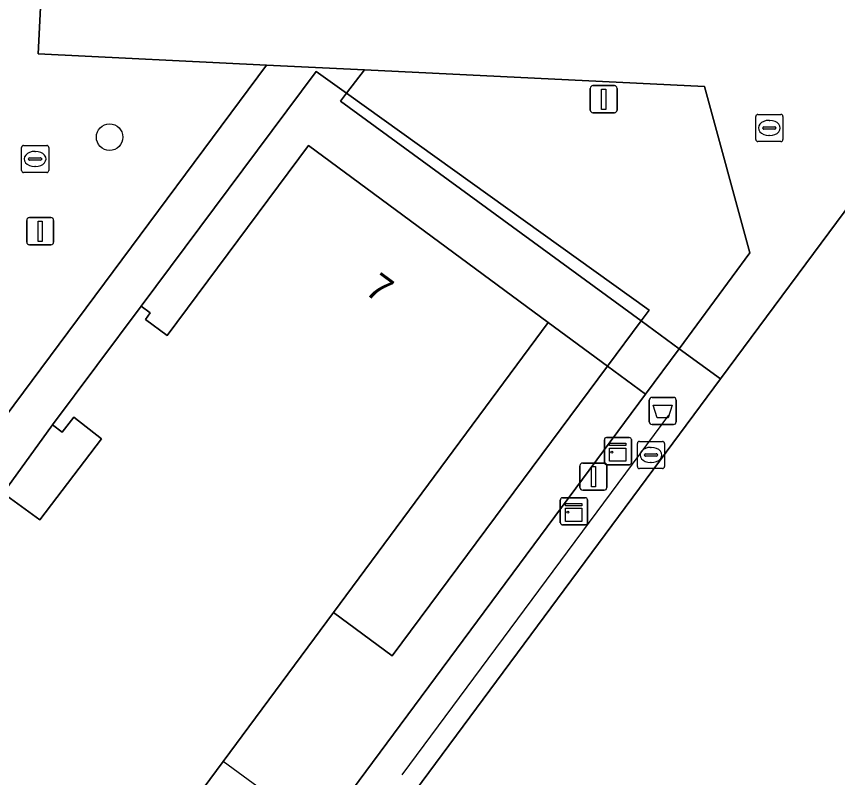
# Model space of a CAD drawing. Extents: x 161758 to 162722, y 384793 to 385405.
# Drawn here: x 162399.64 to 162429.91, y 385008.18 to 385036.24 of the extents above; entities that cross this region are included whole.
import ezdxf

# ---------------------------------------------------------------- set-up
doc = ezdxf.new("R2010")
doc.units = 0
for name, color, linetype in [('IMGEO_Afvalbak', 7, 'Continuous'), ('IMGEO_Boom', 7, 'Continuous'), ('IMGEO_Groenvoorziening', 7, 'Continuous'), ('IMGEO_Hek', 7, 'Continuous'), ('IMGEO_Kast', 7, 'Continuous'), ('IMGEO_Kolk', 7, 'Continuous'), ('IMGEO_Lichtmast', 7, 'Continuous'), ('IMGEO_Pand', 7, 'Continuous'), ('IMGEO_Pand_nummerreeks', 7, 'Continuous'), ('IMGEO_Pand_overbouw', 7, 'Continuous'), ('IMGEO_Rioolput', 7, 'Continuous'), ('IMGEO_Terreindeel_gesloten', 7, 'Continuous'), ('IMGEO_Voetpad_open', 7, 'Continuous')]:
    doc.layers.add(name, color=color, linetype=linetype)

msp = doc.modelspace()

# ---------------------------------------------------------------- linework, layer by layer
at = {"layer": 'IMGEO_Afvalbak'}
for p, q in [((162422.972, 385021.294), (162422.972, 385022.094)), ((162422.972, 385022.094), (162422.972, 385021.294)), ((162423.072, 385022.194), (162423.862, 385022.194)), ((162423.862, 385022.194), (162423.072, 385022.194)), ((162423.962, 385022.094), (162423.962, 385021.294)), ((162423.962, 385021.294), (162423.962, 385022.094)), ((162423.862, 385021.194), (162423.072, 385021.194)), ((162423.072, 385021.194), (162423.862, 385021.194))]:
    msp.add_line(p, q, dxfattribs=at)
msp.add_lwpolyline([(162423.115, 385021.908), (162423.819, 385021.908), (162423.67, 385021.438), (162423.264, 385021.438), (162423.115, 385021.908)], dxfattribs=at)
for centre, start, end in [((162423.072, 385022.094), 90, 180), ((162423.072, 385022.094), 90, 180), ((162423.862, 385022.094), 0, 90), ((162423.862, 385022.094), 360, 90), ((162423.072, 385021.294), 180, 270), ((162423.072, 385021.294), 180, 270), ((162423.862, 385021.294), 270, 0), ((162423.862, 385021.294), 270, 0)]:
    msp.add_arc(centre, 0.1, start, end, dxfattribs=at)
at = {"layer": 'IMGEO_Boom'}
msp.add_circle((162403.077, 385031.789), 0.489, dxfattribs=at)
at = {"layer": 'IMGEO_Groenvoorziening'}
for points in [[(162425.011, 385033.658), (162412.471, 385034.27), (162411.81, 385033.406), (162422.965, 385025.411), (162422.672, 385025.016), (162424.078, 385023.988), (162426.672, 385027.527)], [(162411.81, 385033.406), (162411.592, 385033.121), (162422.672, 385025.016), (162422.965, 385025.411)]]:
    msp.add_lwpolyline(points, close=True, dxfattribs=at)
at = {"layer": 'IMGEO_Hek'}
msp.add_lwpolyline([(162423.674, 385021.538), (162413.845, 385008.282)], dxfattribs=at)
at = {"layer": 'IMGEO_Kast'}
for p, q in [((162421.39, 385020.713), (162422.231, 385020.713)), ((162422.231, 385020.713), (162421.39, 385020.713)), ((162421.315, 385019.788), (162421.315, 385020.629)), ((162421.315, 385020.629), (162421.315, 385019.788)), ((162422.315, 385020.638), (162422.315, 385019.797)), ((162422.315, 385019.797), (162422.315, 385020.638)), ((162422.24, 385019.713), (162421.399, 385019.713)), ((162421.399, 385019.713), (162422.24, 385019.713)), ((162419.692, 385017.571), (162419.692, 385018.412)), ((162419.692, 385018.412), (162419.692, 385017.571)), ((162419.767, 385018.496), (162420.608, 385018.496)), ((162420.608, 385018.496), (162419.767, 385018.496)), ((162420.692, 385018.421), (162420.692, 385017.58)), ((162420.692, 385017.58), (162420.692, 385018.421)), ((162420.617, 385017.496), (162419.776, 385017.496)), ((162419.776, 385017.496), (162420.617, 385017.496))]:
    msp.add_line(p, q, dxfattribs=at)
for points in [[(162421.51, 385020.503), (162422.11, 385020.503), (162422.11, 385020.418), (162421.51, 385020.418), (162421.51, 385020.503)], [(162421.51, 385020.328), (162422.11, 385020.328), (162422.11, 385019.839), (162421.51, 385019.839), (162421.51, 385020.328)], [(162419.887, 385018.286), (162420.487, 385018.286), (162420.487, 385018.201), (162419.887, 385018.201), (162419.887, 385018.286)], [(162419.887, 385018.111), (162420.487, 385018.111), (162420.487, 385017.622), (162419.887, 385017.622), (162419.887, 385018.111)]]:
    msp.add_lwpolyline(points, dxfattribs=at)
for centre in [(162421.594, 385020.177), (162419.971, 385017.96)]:
    msp.add_circle(centre, 0.0377, dxfattribs=at)
for centre, start, end in [((162421.393, 385020.635), 92.4484, 184.2845), ((162421.393, 385020.635), 92.4484, 184.2845), ((162422.237, 385020.635), 2.4484, 94.2845), ((162422.237, 385020.635), 2.4484, 94.2845), ((162422.237, 385019.791), 272.4484, 4.2845), ((162422.237, 385019.791), 272.4484, 4.2845), ((162421.393, 385019.791), 182.4484, 274.2845), ((162421.393, 385019.791), 182.4484, 274.2845), ((162419.77, 385018.418), 92.4484, 184.2845), ((162419.77, 385018.418), 92.4484, 184.2845), ((162420.614, 385018.418), 2.4484, 94.2845), ((162420.614, 385018.418), 2.4484, 94.2845), ((162419.77, 385017.574), 182.4484, 274.2845), ((162419.77, 385017.574), 182.4484, 274.2845), ((162420.614, 385017.574), 272.4484, 4.2845), ((162420.614, 385017.574), 272.4484, 4.2845)]:
    msp.add_arc(centre, 0.0779, start, end, dxfattribs=at)
at = {"layer": 'IMGEO_Kolk'}
for p, q in [((162399.83, 385030.558), (162399.83, 385031.41)), ((162399.905, 385031.484), (162400.757, 385031.484)), ((162400.831, 385031.41), (162400.831, 385030.558)), ((162400.132, 385031.027), (162400.53, 385031.027)), ((162400.318, 385031.264), (162400.343, 385031.264)), ((162400.089, 385030.978), (162400.089, 385030.99)), ((162400.527, 385030.941), (162400.129, 385030.941)), ((162400.341, 385030.704), (162400.316, 385030.704)), ((162400.573, 385030.99), (162400.573, 385030.978)), ((162400.757, 385030.484), (162399.905, 385030.484)), ((162422.531, 385019.645), (162422.531, 385020.497)), ((162422.606, 385020.571), (162423.458, 385020.571)), ((162423.532, 385020.497), (162423.532, 385019.645)), ((162422.833, 385020.114), (162423.231, 385020.114)), ((162423.019, 385020.351), (162423.044, 385020.351)), ((162422.79, 385020.065), (162422.79, 385020.077)), ((162423.228, 385020.028), (162422.83, 385020.028)), ((162423.274, 385020.077), (162423.274, 385020.065)), ((162423.458, 385019.571), (162422.606, 385019.571)), ((162423.042, 385019.791), (162423.017, 385019.791))]:
    msp.add_line(p, q, dxfattribs=at)
for points in [[(162399.83, 385030.558), (162399.83, 385031.41)], [(162399.905, 385031.484), (162400.757, 385031.484)], [(162400.831, 385031.41), (162400.831, 385030.558)], [(162400.757, 385030.484), (162399.905, 385030.484)], [(162422.531, 385019.645), (162422.531, 385020.497)], [(162422.606, 385020.571), (162423.458, 385020.571)], [(162423.532, 385020.497), (162423.532, 385019.645)], [(162423.458, 385019.571), (162422.606, 385019.571)]]:
    msp.add_lwpolyline(points, dxfattribs=at)
for centre, radius, start, end in [((162399.907, 385031.408), 0.0765, 91.552, 178.448), ((162399.907, 385031.408), 0.0765, 91.552, 178.448), ((162400.755, 385031.408), 0.0765, 1.552, 88.448), ((162400.755, 385031.408), 0.0765, 1.552, 88.448), ((162400.129, 385030.987), 0.0403, 85.8775, 175.7526), ((162400.534, 385030.989), 0.0386, 1.7309, 96.639), ((162400.126, 385030.977), 0.0366, 178.938, 274.7102), ((162400.53, 385030.984), 0.043, 264.8664, 352.4533), ((162399.907, 385030.56), 0.0765, 181.552, 268.448), ((162399.907, 385030.56), 0.0765, 181.552, 268.448), ((162400.755, 385030.56), 0.0765, 271.552, 358.448), ((162400.755, 385030.56), 0.0765, 271.552, 358.448), ((162422.608, 385020.495), 0.0765, 91.552, 178.448), ((162422.608, 385020.495), 0.0765, 91.552, 178.448), ((162423.456, 385020.495), 0.0765, 1.552, 88.448), ((162423.456, 385020.495), 0.0765, 1.552, 88.448), ((162422.83, 385020.074), 0.0403, 85.8775, 175.7526), ((162423.235, 385020.076), 0.0386, 1.7309, 96.639), ((162422.827, 385020.064), 0.0366, 178.938, 274.7102), ((162423.231, 385020.071), 0.043, 264.8664, 352.4533), ((162422.608, 385019.647), 0.0765, 181.552, 268.448), ((162422.608, 385019.647), 0.0765, 181.552, 268.448), ((162423.456, 385019.647), 0.0765, 271.552, 358.448), ((162423.456, 385019.647), 0.0765, 271.552, 358.448)]:
    msp.add_arc(centre, radius, start, end, dxfattribs=at)
for centre, major_axis, ratio, start_param, end_param in [((162400.317, 385030.984), (-0.387, 0.002), 0.722429, 4.712389, 7.853982), ((162400.342, 385030.984), (-0.39, 0.002), 0.717154, 1.570796, 4.712389), ((162423.018, 385020.071), (-0.387, 0.002), 0.722429, 4.712389, 7.853982), ((162423.043, 385020.071), (-0.39, 0.002), 0.717154, 1.570796, 4.712389)]:
    msp.add_ellipse(centre, major_axis=major_axis, ratio=ratio, start_param=start_param, end_param=end_param, dxfattribs=at)
at = {"layer": 'IMGEO_Lichtmast'}
for p, q in [((162420.795, 385032.788), (162420.795, 385033.588)), ((162420.795, 385033.588), (162420.795, 385032.788)), ((162420.895, 385033.688), (162421.685, 385033.688)), ((162421.685, 385033.688), (162420.895, 385033.688)), ((162421.785, 385033.588), (162421.785, 385032.788)), ((162421.785, 385032.788), (162421.785, 385033.588)), ((162421.685, 385032.688), (162420.895, 385032.688)), ((162420.895, 385032.688), (162421.685, 385032.688)), ((162400.023, 385027.922), (162400.023, 385028.722)), ((162400.023, 385028.722), (162400.023, 385027.922)), ((162400.123, 385028.822), (162400.913, 385028.822)), ((162400.913, 385028.822), (162400.123, 385028.822)), ((162401.013, 385028.722), (162401.013, 385027.922)), ((162401.013, 385027.922), (162401.013, 385028.722)), ((162400.913, 385027.822), (162400.123, 385027.822)), ((162400.123, 385027.822), (162400.913, 385027.822)), ((162420.417, 385018.875), (162420.417, 385019.675)), ((162420.417, 385019.675), (162420.417, 385018.875)), ((162420.517, 385019.775), (162421.307, 385019.775)), ((162421.307, 385019.775), (162420.517, 385019.775)), ((162421.407, 385019.675), (162421.407, 385018.875)), ((162421.407, 385018.875), (162421.407, 385019.675)), ((162421.307, 385018.775), (162420.517, 385018.775)), ((162420.517, 385018.775), (162421.307, 385018.775))]:
    msp.add_line(p, q, dxfattribs=at)
for points in [[(162421.215, 385033.563), (162421.365, 385033.563), (162421.365, 385032.813), (162421.215, 385032.813), (162421.215, 385033.563)], [(162400.443, 385028.697), (162400.593, 385028.697), (162400.593, 385027.947), (162400.443, 385027.947), (162400.443, 385028.697)], [(162420.837, 385019.65), (162420.987, 385019.65), (162420.987, 385018.9), (162420.837, 385018.9), (162420.837, 385019.65)]]:
    msp.add_lwpolyline(points, dxfattribs=at)
for centre, start, end in [((162420.895, 385033.588), 90, 180), ((162420.895, 385033.588), 90, 180), ((162421.685, 385033.588), 0, 90), ((162421.685, 385033.588), 360, 90), ((162420.895, 385032.788), 180, 270), ((162420.895, 385032.788), 180, 270), ((162421.685, 385032.788), 270, 0), ((162421.685, 385032.788), 270, 0), ((162400.123, 385028.722), 90, 180), ((162400.123, 385028.722), 90, 180), ((162400.913, 385028.722), 0, 90), ((162400.913, 385028.722), 360, 90), ((162400.123, 385027.922), 180, 270), ((162400.123, 385027.922), 180, 270), ((162400.913, 385027.922), 270, 0), ((162400.913, 385027.922), 270, 0), ((162420.517, 385019.675), 90, 180), ((162420.517, 385019.675), 90, 180), ((162421.307, 385019.675), 0, 90), ((162421.307, 385019.675), 360, 90), ((162420.517, 385018.875), 180, 270), ((162420.517, 385018.875), 180, 270), ((162421.307, 385018.875), 270, 0), ((162421.307, 385018.875), 270, 0)]:
    msp.add_arc(centre, 0.1, start, end, dxfattribs=at)
at = {"layer": 'IMGEO_Pand'}
msp.add_lwpolyline([(162380.077, 384972.07), (162382.369, 384975.165), (162407.264, 385008.775), (162411.333, 385014.268), (162419.249, 385024.957), (162410.404, 385031.486), (162405.199, 385024.476), (162404.396, 385025.072), (162404.576, 385025.313), (162404.244, 385025.561), (162400.976, 385021.188), (162401.324, 385020.915), (162401.756, 385021.466), (162402.779, 385020.663), (162400.501, 385017.681), (162399.158, 385018.667), (162397.863, 385016.883), (162398.969, 385016.075), (162373.363, 384981.527), (162372.307, 384982.33), (162357.523, 384962.376), (162358.603, 384961.577), (162354.028, 384955.397), (162362.815, 384948.782)], close=True, dxfattribs=at)
at = {"layer": 'IMGEO_Pand_overbouw'}
for points in [[(162411.333, 385014.268), (162413.495, 385012.661), (162421.433, 385023.347), (162422.965, 385025.411), (162411.81, 385033.406), (162410.688, 385034.211), (162404.244, 385025.561), (162404.576, 385025.313), (162404.396, 385025.072), (162405.199, 385024.476), (162410.404, 385031.486), (162419.249, 385024.957)], [(162399.158, 385018.667), (162400.501, 385017.681), (162402.779, 385020.663), (162401.756, 385021.466), (162401.324, 385020.915), (162400.976, 385021.188)], [(162382.369, 384975.165), (162384.52, 384973.558), (162409.423, 385007.181), (162407.264, 385008.775)]]:
    msp.add_lwpolyline(points, close=True, dxfattribs=at)
at = {"layer": 'IMGEO_Rioolput'}
for p, q in [((162426.898, 385031.701), (162426.898, 385032.553)), ((162426.973, 385032.627), (162427.825, 385032.627)), ((162427.899, 385032.553), (162427.899, 385031.701)), ((162427.386, 385032.407), (162427.411, 385032.407)), ((162427.157, 385032.121), (162427.157, 385032.133)), ((162427.595, 385032.084), (162427.197, 385032.084)), ((162427.2, 385032.17), (162427.598, 385032.17)), ((162427.641, 385032.133), (162427.641, 385032.121)), ((162427.825, 385031.627), (162426.973, 385031.627)), ((162427.409, 385031.847), (162427.384, 385031.847))]:
    msp.add_line(p, q, dxfattribs=at)
for points in [[(162426.898, 385031.701), (162426.898, 385032.553)], [(162426.973, 385032.627), (162427.825, 385032.627)], [(162427.899, 385032.553), (162427.899, 385031.701)], [(162427.825, 385031.627), (162426.973, 385031.627)]]:
    msp.add_lwpolyline(points, dxfattribs=at)
for centre, radius, start, end in [((162426.975, 385032.551), 0.0765, 91.552, 178.448), ((162426.975, 385032.551), 0.0765, 91.552, 178.448), ((162427.823, 385032.551), 0.0765, 1.552, 88.448), ((162427.823, 385032.551), 0.0765, 1.552, 88.448), ((162427.197, 385032.13), 0.0403, 85.8775, 175.7526), ((162427.194, 385032.12), 0.0366, 178.938, 274.7102), ((162427.598, 385032.127), 0.043, 264.8664, 352.4533), ((162427.602, 385032.132), 0.0386, 1.7309, 96.639), ((162426.975, 385031.703), 0.0765, 181.552, 268.448), ((162426.975, 385031.703), 0.0765, 181.552, 268.448), ((162427.823, 385031.703), 0.0765, 271.552, 358.448), ((162427.823, 385031.703), 0.0765, 271.552, 358.448)]:
    msp.add_arc(centre, radius, start, end, dxfattribs=at)
for centre, major_axis, ratio, start_param, end_param in [((162427.385, 385032.127), (-0.387, 0.002), 0.722429, 4.712389, 7.853982), ((162427.41, 385032.127), (-0.39, 0.002), 0.717154, 1.570796, 4.712389)]:
    msp.add_ellipse(centre, major_axis=major_axis, ratio=ratio, start_param=start_param, end_param=end_param, dxfattribs=at)
at = {"layer": 'IMGEO_Terreindeel_gesloten'}
msp.add_lwpolyline([(162433.416, 385017.003), (162438.682, 385023.883), (162432.687, 385028.333), (162430.723, 385029.79), (162425.597, 385022.88), (162350.849, 384921.99), (162348.561, 384918.914), (162353.879, 384914.754)], dxfattribs=at)
at = {"layer": 'IMGEO_Voetpad_open'}
for points in [[(162404.495, 385069.287), (162405.806, 385097.791), (162404.241, 385097.842), (162404.247, 385098.213), (162399.452, 385098.409), (162395.555, 385016.551), (162408.86, 385034.446), (162400.443, 385034.857), (162400.64, 385038.778), (162402.942, 385038.647), (162404.199, 385063.991), (162405.414, 385063.918), (162405.573, 385068.801), (162405.588, 385069.236)], [(162436.14, 385037.094), (162411.738, 385038.219), (162408.658, 385038.361), (162404.461, 385038.567), (162404.313, 385038.575), (162404.024, 385038.585), (162402.942, 385038.647), (162400.64, 385038.778), (162400.443, 385034.857), (162408.86, 385034.446), (162412.471, 385034.27), (162425.011, 385033.658), (162426.672, 385027.527), (162424.078, 385023.988), (162425.597, 385022.88), (162430.723, 385029.79), (162432.406, 385032.061), (162433.949, 385034.141)], [(162410.688, 385034.211), (162411.81, 385033.406), (162412.471, 385034.27), (162408.86, 385034.446), (162395.555, 385016.551), (162350.358, 384955.479), (162350.245, 384953.178), (162360.479, 384945.625), (162361.851, 384947.48), (162351.822, 384954.748), (162357.523, 384962.376), (162372.307, 384982.33), (162373.363, 384981.527), (162398.969, 385016.075), (162397.863, 385016.883), (162399.158, 385018.667), (162400.976, 385021.188), (162404.244, 385025.561)], [(162404.244, 385025.561), (162404.576, 385025.313), (162404.396, 385025.072), (162405.199, 385024.476), (162410.404, 385031.486), (162419.249, 385024.957), (162421.433, 385023.347), (162422.672, 385025.016), (162411.592, 385033.121), (162411.81, 385033.406), (162410.688, 385034.211)], [(162421.433, 385023.347), (162419.249, 385024.957), (162411.333, 385014.268), (162413.495, 385012.661)], [(162424.078, 385023.988), (162422.672, 385025.016), (162421.433, 385023.347), (162422.828, 385022.318)], [(162360.185, 384940.192), (162358.509, 384937.925), (162357.787, 384936.949), (162355.85, 384934.33), (162348.853, 384924.868), (162348.561, 384918.914), (162350.849, 384921.99), (162425.597, 385022.88), (162424.078, 385023.988), (162422.828, 385022.318), (162366.338, 384946.103), (162364.988, 384947.13), (162364.062, 384945.878), (162361.851, 384947.48), (162360.479, 384945.625), (162362.889, 384943.847), (162360.798, 384941.02)], [(162422.828, 385022.318), (162421.433, 385023.347), (162413.495, 385012.661), (162411.333, 385014.268), (162407.264, 385008.775), (162382.369, 384975.165), (162380.077, 384972.07), (162382.246, 384970.467), (162364.988, 384947.13), (162366.338, 384946.103)], [(162399.158, 385018.667), (162400.501, 385017.681), (162402.779, 385020.663), (162401.756, 385021.466), (162401.324, 385020.915), (162400.976, 385021.188)]]:
    msp.add_lwpolyline(points, close=True, dxfattribs=at)

# ---------------------------------------------------------------- texts
at = {"layer": 'IMGEO_Pand_nummerreeks'}
msp.add_text('7', height=1, rotation=323.4627, dxfattribs=at).set_placement((162412.442, 385026.049))

doc.saveas('drawing.dxf')
